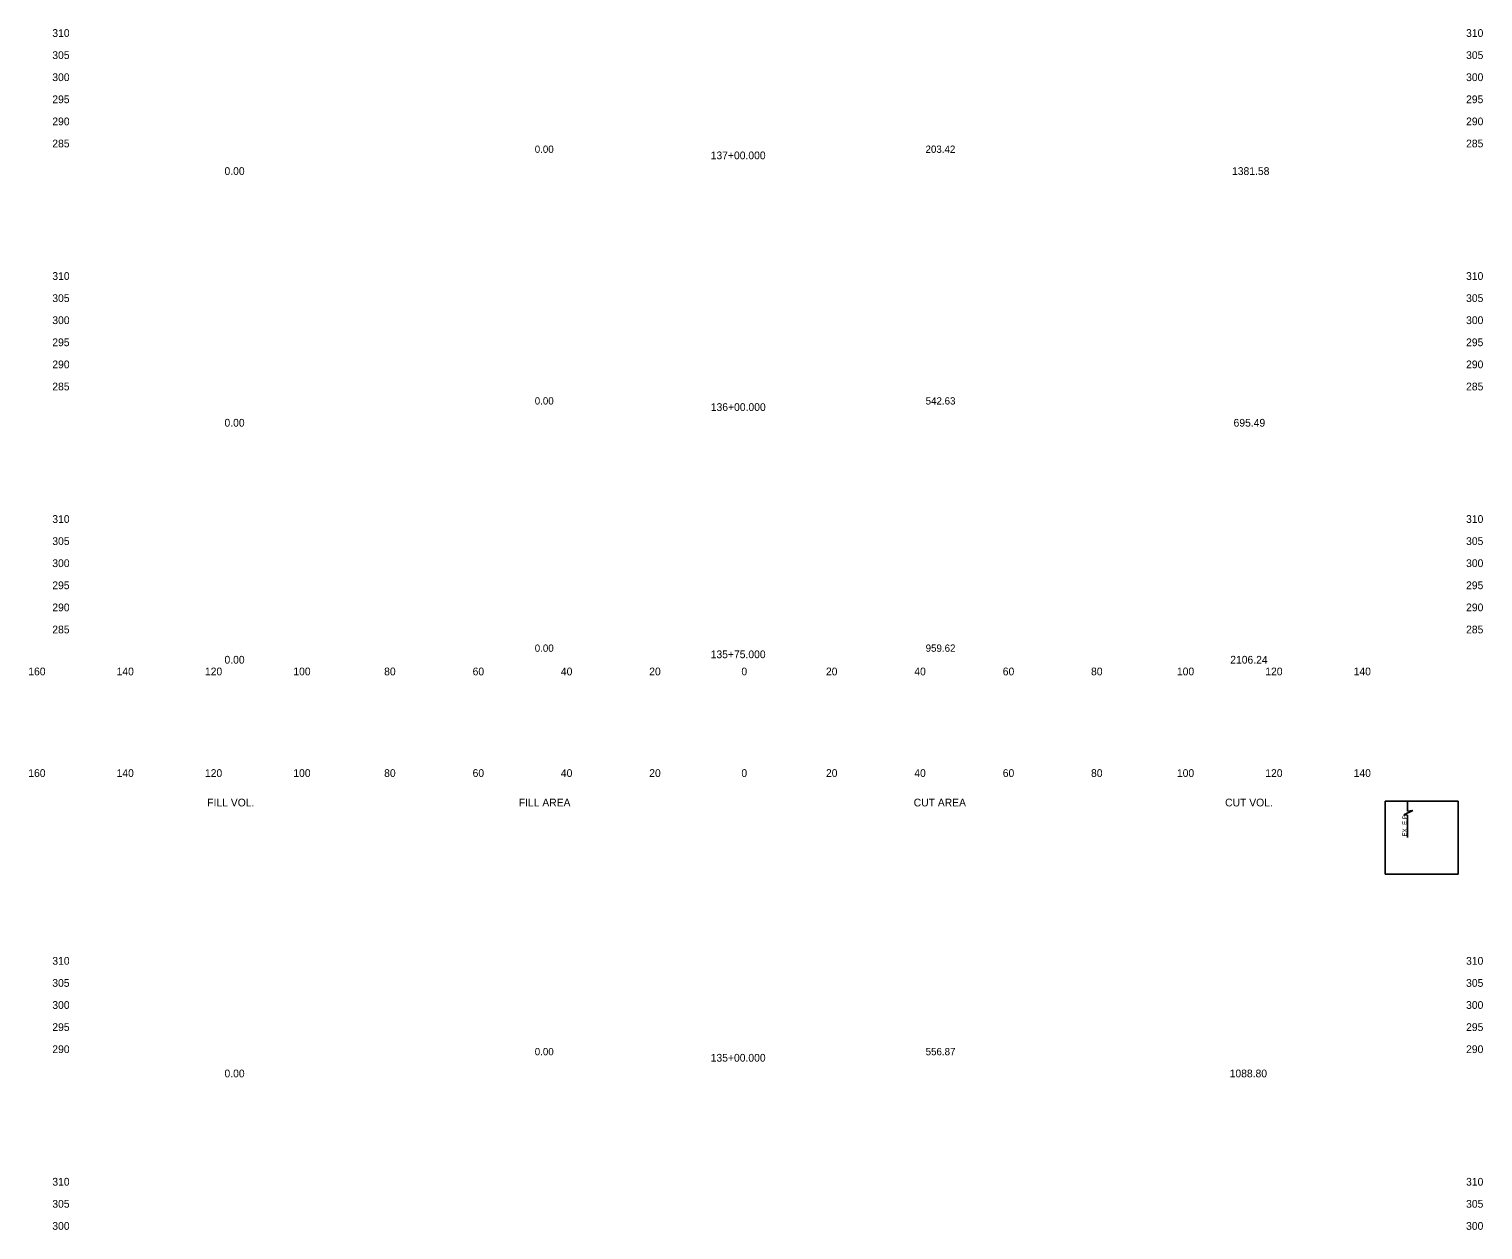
# Model space of a CAD drawing. Extents: x 21477 to 21806, y 6470 to 11049.
# Drawn here: x 21477.1 to 21806.1, y 9334.8 to 9606.6 of the extents above; entities that cross this region are included whole.
import ezdxf

# ---------------------------------------------------------------- set-up
doc = ezdxf.new("R2010")
doc.units = 0
for name, color, linetype in [('SHEET_CONSULTANT_STAMP', 7, 'Continuous'), ('X_TRANS_TX', 7, 'Continuous'), ('XS_P_FINISHED_GRADE_ELEV_TX', 7, 'Continuous'), ('XS_SHEET_EW_TX_AREA', 7, 'Continuous'), ('XS_SHEET_EW_TX_VOLUME', 7, 'Continuous'), ('XS_SHEET_LABELS_ELEVATION', 7, 'Continuous'), ('XS_SHEET_LABELS_OFFSET', 7, 'Continuous'), ('XS_SHEET_LABELS_STATION', 7, 'Continuous'), ('XS_SHEET_TX', 7, 'Continuous')]:
    doc.layers.add(name, color=color, linetype=linetype)

msp = doc.modelspace()

# ---------------------------------------------------------------- linework, layer by layer
at = {"layer": 'SHEET_CONSULTANT_STAMP'}
msp.add_lwpolyline([(21784.04, 9415.34), (21800.54, 9415.34), (21800.54, 9431.84), (21784.04, 9431.84)], close=True, dxfattribs=at)
at = {"layer": 'XS_P_FINISHED_GRADE_ELEV_TX'}
for p, q in [((21789.09, 9431.86), (21789.08, 9429.62)), ((21790.27, 9429.72), (21788.27, 9428.75)), ((21788.27, 9428.75), (21789.1, 9428.72)), ((21789.08, 9429.62), (21790.27, 9429.72)), ((21789.1, 9428.72), (21789.1, 9423.63))]:
    msp.add_line(p, q, dxfattribs=at)

# ---------------------------------------------------------------- texts
at = {"layer": 'X_TRANS_TX'}
msp.add_text('EX. E.P.', height=1, rotation=90, dxfattribs=at).set_placement((21788.94, 9423.86))
at = {"layer": 'XS_SHEET_EW_TX_AREA'}
for s, p in [(' 0.00 ', (21590.92, 9578.6)), (' 203.42 ', (21679.37, 9578.6)), (' 0.00 ', (21590.92, 9521.63)), (' 542.63 ', (21679.4, 9521.63)), (' 0.00 ', (21590.92, 9465.67)), (' 959.62 ', (21679.4, 9465.67)), (' 0.00 ', (21590.92, 9374.35)), (' 556.87 ', (21679.4, 9374.35))]:
    msp.add_text(s, height=1.65, dxfattribs=at).set_placement(p)
at = {"layer": 'XS_SHEET_EW_TX_VOLUME'}
for s, p in [(' 0.00 ', (21520.66, 9573.6)), (' 1381.58 ', (21748.71, 9573.6)), (' 0.00 ', (21520.66, 9516.63)), (' 695.49 ', (21749.06, 9516.63)), (' 0.00 ', (21520.66, 9462.99)), (' 2106.24 ', (21748.31, 9462.99)), (' 0.00 ', (21520.66, 9369.35)), (' 1088.80 ', (21748.18, 9369.35))]:
    msp.add_text(s, height=1.75, dxfattribs=at).set_placement(p)
at = {"layer": 'XS_SHEET_LABELS_ELEVATION'}
for s, p in [('  310  ', (21481.04, 9604.84)), ('  310  ', (21801.04, 9604.84)), ('  305  ', (21481.04, 9599.84)), ('  305  ', (21801.04, 9599.84)), ('  300  ', (21481.04, 9594.84)), ('  300  ', (21801.04, 9594.84)), ('  295  ', (21481.04, 9589.84)), ('  295  ', (21801.04, 9589.84)), ('  290  ', (21481.04, 9584.84)), ('  290  ', (21801.04, 9584.84)), ('  285  ', (21481.04, 9579.84)), ('  285  ', (21801.04, 9579.84)), ('  310  ', (21481.04, 9549.84)), ('  310  ', (21801.04, 9549.84)), ('  305  ', (21481.04, 9544.84)), ('  305  ', (21801.04, 9544.84)), ('  300  ', (21481.04, 9539.84)), ('  300  ', (21801.04, 9539.84)), ('  295  ', (21481.04, 9534.84)), ('  295  ', (21801.04, 9534.84)), ('  290  ', (21481.04, 9529.84)), ('  290  ', (21801.04, 9529.84)), ('  285  ', (21481.04, 9524.84)), ('  285  ', (21801.04, 9524.84)), ('  310  ', (21481.04, 9494.84)), ('  310  ', (21801.04, 9494.84)), ('  305  ', (21481.04, 9489.84)), ('  305  ', (21801.04, 9489.84)), ('  300  ', (21481.04, 9484.84)), ('  300  ', (21801.04, 9484.84)), ('  295  ', (21481.04, 9479.84)), ('  295  ', (21801.04, 9479.84)), ('  290  ', (21481.04, 9474.84)), ('  290  ', (21801.04, 9474.84)), ('  285  ', (21481.04, 9469.84)), ('  285  ', (21801.04, 9469.84)), ('  310  ', (21481.04, 9394.84)), ('  310  ', (21801.04, 9394.84)), ('  305  ', (21481.04, 9389.84)), ('  305  ', (21801.04, 9389.84)), ('  300  ', (21481.04, 9384.84)), ('  300  ', (21801.04, 9384.84)), ('  295  ', (21481.04, 9379.84)), ('  295  ', (21801.04, 9379.84)), ('  290  ', (21481.04, 9374.84)), ('  290  ', (21801.04, 9374.84)), ('  310  ', (21481.04, 9344.84)), ('  310  ', (21801.04, 9344.84)), ('  305  ', (21481.04, 9339.84)), ('  305  ', (21801.04, 9339.84)), ('  300  ', (21481.04, 9334.84)), ('  300  ', (21801.04, 9334.84))]:
    msp.add_text(s, height=1.75, dxfattribs=at).set_placement(p)
at = {"layer": 'XS_SHEET_LABELS_OFFSET'}
for s, p in [('  160  ', (21475.6, 9460.34)), ('  140  ', (21495.59, 9460.34)), ('  120  ', (21515.59, 9460.34)), ('  100  ', (21535.59, 9460.34)), ('  80  ', (21556.15, 9460.34)), ('  60  ', (21576.17, 9460.34)), ('  40  ', (21596.15, 9460.34)), ('  20  ', (21616.15, 9460.34)), ('  0  ', (21637.01, 9460.34)), ('  0  ', (21637.01, 9460.34)), ('  20  ', (21656.15, 9460.34)), ('  40  ', (21676.15, 9460.34)), ('  60  ', (21696.17, 9460.34)), ('  80  ', (21716.15, 9460.34)), ('  100  ', (21735.59, 9460.34)), ('  120  ', (21755.59, 9460.34)), ('  140  ', (21775.59, 9460.34)), ('  160  ', (21475.6, 9437.34)), ('  140  ', (21495.59, 9437.34)), ('  120  ', (21515.59, 9437.34)), ('  100  ', (21535.59, 9437.34)), ('  80  ', (21556.15, 9437.34)), ('  60  ', (21576.17, 9437.34)), ('  40  ', (21596.15, 9437.34)), ('  20  ', (21616.15, 9437.34)), ('  0  ', (21637.01, 9437.34)), ('  0  ', (21637.01, 9437.34)), ('  20  ', (21656.15, 9437.34)), ('  40  ', (21676.15, 9437.34)), ('  60  ', (21696.17, 9437.34)), ('  80  ', (21716.15, 9437.34)), ('  100  ', (21735.59, 9437.34)), ('  120  ', (21755.59, 9437.34)), ('  140  ', (21775.59, 9437.34))]:
    msp.add_text(s, height=1.75, dxfattribs=at).set_placement(p)
at = {"layer": 'XS_SHEET_LABELS_STATION'}
for s, p in [('  137+00.000  ', (21630.06, 9577.15)), ('  136+00.000  ', (21630.08, 9520.18)), ('  135+75.000  ', (21630.06, 9464.22)), ('  135+00.000  ', (21630.06, 9372.9))]:
    msp.add_text(s, height=1.75, dxfattribs=at).set_placement(p)
at = {"layer": 'XS_SHEET_TX'}
for s, p in [('FILL VOL.', (21517.41, 9430.67)), ('FILL AREA', (21587.92, 9430.67)), ('CUT AREA', (21677.31, 9430.67)), ('CUT VOL.', (21747.8, 9430.67))]:
    msp.add_text(s, height=1.75, dxfattribs=at).set_placement(p)

doc.saveas('drawing.dxf')
